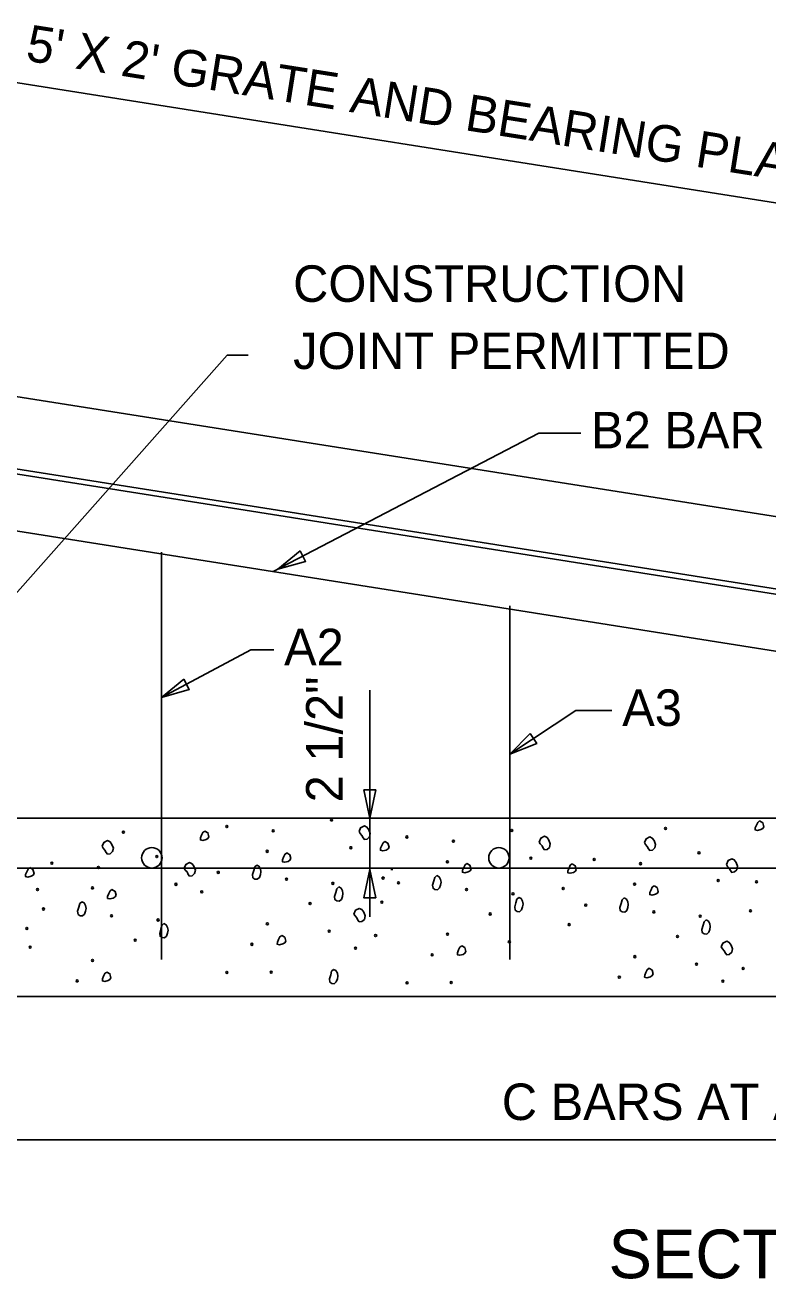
# Model space of a CAD drawing. Extents: x -439.1 to -407.9, y -458.1 to -436.2.
# Drawn here: x -435.33 to -432.28, y -450.33 to -445.18 of the extents above; entities that cross this region are included whole.
import ezdxf

# ---------------------------------------------------------------- set-up
doc = ezdxf.new("R2010")
doc.units = 0
doc.layers.add('Level 4', color=7, linetype='Continuous')
doc.layers.add('Level 45', color=7, linetype='Continuous')

msp = doc.modelspace()

# ---------------------------------------------------------------- linework, layer by layer
at = {"layer": 'Level 4'}
for p, q in [((-435.643, -445.37), (-430.4863, -446.1867)), ((-438.971, -446.1333), (-425.1939, -448.3149)), ((-436.1881, -448.4367), (-434.502, -446.5338)), ((-434.502, -446.5338), (-434.4147, -446.5338)), ((-434.3122, -447.4238), (-433.2211, -446.854)), ((-433.2211, -446.854), (-433.0485, -446.854)), ((-435.9228, -446.9132), (-430.76, -447.7311)), ((-435.9281, -446.9342), (-430.7645, -447.7516)), ((-436.074, -447.1452), (-430.0008, -448.107)), ((-434.771, -447.3437), (-434.771, -449.0184)), ((-433.3398, -447.5642), (-433.3398, -449.0184)), ((-434.771, -447.9417), (-434.4048, -447.7456)), ((-434.4048, -447.7456), (-434.3101, -447.7456)), ((-433.9151, -448.8431), (-433.9151, -447.9106)), ((-433.3398, -448.1734), (-433.0688, -447.995)), ((-433.0688, -447.995), (-432.9207, -447.995)), ((-435.9228, -448.4367), (-425.1939, -448.4367)), ((-436.4384, -448.6425), (-430.5353, -448.6425)), ((-433.8294, -448.6488), (-433.8206, -448.6488)), ((-436.7019, -449.1696), (-425.1939, -449.1696)), ((-425.1938, -449.759), (-436.7024, -449.759))]:
    msp.add_line(p, q, dxfattribs=at)
for points in [[(-434.2018, -447.3389), (-434.2936, -447.4141), (-434.1794, -447.3817)], [(-434.6799, -447.8656), (-434.771, -447.9417), (-434.6572, -447.9081)], [(-433.2561, -448.0893), (-433.3398, -448.1734), (-433.2295, -448.1296)], [(-433.9393, -448.3209), (-433.9151, -448.437), (-433.891, -448.3209)], [(-433.9596, -448.4922), (-433.953, -448.4764), (-433.9375, -448.4688), (-433.9272, -448.4737), (-433.9193, -448.4844), (-433.9136, -448.4996), (-433.9167, -448.5142), (-433.9268, -448.5231), (-433.9375, -448.5246), (-433.943, -448.5176), (-433.9479, -448.5078), (-433.9549, -448.5002), (-433.9596, -448.4922)], [(-432.3136, -448.4487), (-432.3214, -448.4546), (-432.3266, -448.4656), (-432.3314, -448.4768), (-432.3318, -448.4851), (-432.3223, -448.4874), (-432.3084, -448.4838), (-432.3007, -448.479), (-432.2967, -448.4721), (-432.301, -448.4561), (-432.3136, -448.4487)], [(-435.0152, -448.5528), (-435.0086, -448.537), (-434.9931, -448.5294), (-434.9828, -448.5343), (-434.9749, -448.545), (-434.9692, -448.5602), (-434.9723, -448.5748), (-434.9824, -448.5837), (-434.9931, -448.5852), (-434.9985, -448.5782), (-435.0035, -448.5683), (-435.0105, -448.5608), (-435.0152, -448.5528)], [(-434.5934, -448.4899), (-434.6012, -448.4958), (-434.6064, -448.5068), (-434.6112, -448.518), (-434.6116, -448.5263), (-434.6021, -448.5286), (-434.5882, -448.525), (-434.5805, -448.5202), (-434.5765, -448.5133), (-434.5808, -448.4973), (-434.5934, -448.4899)], [(-433.2195, -448.5352), (-433.2129, -448.5195), (-433.1974, -448.5118), (-433.1871, -448.5167), (-433.1793, -448.5274), (-433.1736, -448.5427), (-433.1767, -448.5573), (-433.1867, -448.5661), (-433.1974, -448.5677), (-433.2029, -448.5606), (-433.2078, -448.5508), (-433.2148, -448.5432), (-433.2195, -448.5352)], [(-432.787, -448.5374), (-432.7804, -448.5216), (-432.7649, -448.514), (-432.7546, -448.5189), (-432.7467, -448.5296), (-432.7411, -448.5449), (-432.7442, -448.5594), (-432.7542, -448.5683), (-432.7649, -448.5698), (-432.7704, -448.5628), (-432.7753, -448.553), (-432.7823, -448.5454), (-432.787, -448.5374)], [(-434.2564, -448.5799), (-434.2642, -448.5858), (-434.2694, -448.5968), (-434.2741, -448.608), (-434.2746, -448.6163), (-434.2651, -448.6186), (-434.2512, -448.615), (-434.2434, -448.6102), (-434.2395, -448.6033), (-434.2438, -448.5874), (-434.2564, -448.5799)], [(-433.8534, -448.533), (-433.8611, -448.5388), (-433.8663, -448.5498), (-433.8711, -448.5611), (-433.8715, -448.5693), (-433.8621, -448.5716), (-433.8482, -448.568), (-433.8404, -448.5632), (-433.8365, -448.5563), (-433.8407, -448.5404), (-433.8534, -448.533)], [(-434.6781, -448.6428), (-434.6715, -448.627), (-434.6561, -448.6194), (-434.6458, -448.6243), (-434.6379, -448.635), (-434.6322, -448.6502), (-434.6353, -448.6648), (-434.6453, -448.6737), (-434.6561, -448.6752), (-434.6615, -448.6682), (-434.6664, -448.6583), (-434.6734, -448.6508), (-434.6781, -448.6428)], [(-434.3802, -448.63), (-434.3881, -448.6375), (-434.3919, -448.6521), (-434.3972, -448.6689), (-434.3958, -448.682), (-434.3876, -448.6876), (-434.3776, -448.6884), (-434.3692, -448.6811), (-434.3646, -448.669), (-434.3628, -448.6572), (-434.3646, -448.6456), (-434.3707, -448.6348), (-434.3802, -448.63)], [(-433.5163, -448.623), (-433.5241, -448.6289), (-433.5293, -448.6398), (-433.534, -448.6511), (-433.5345, -448.6593), (-433.525, -448.6616), (-433.5111, -448.658), (-433.5033, -448.6532), (-433.4994, -448.6463), (-433.5037, -448.6304), (-433.5163, -448.623)], [(-433.0838, -448.6251), (-433.0916, -448.631), (-433.0968, -448.642), (-433.1015, -448.6532), (-433.102, -448.6615), (-433.0925, -448.6638), (-433.0786, -448.6602), (-433.0708, -448.6554), (-433.0669, -448.6485), (-433.0712, -448.6326), (-433.0838, -448.6251)], [(-432.4499, -448.6274), (-432.4434, -448.6116), (-432.4279, -448.604), (-432.4176, -448.6089), (-432.4097, -448.6196), (-432.404, -448.6349), (-432.4071, -448.6494), (-432.4172, -448.6583), (-432.4279, -448.6598), (-432.4333, -448.6528), (-432.4383, -448.643), (-432.4453, -448.6354), (-432.4499, -448.6274)], [(-435.312, -448.6405), (-435.3198, -448.6464), (-435.325, -448.6574), (-435.3297, -448.6686), (-435.3302, -448.6769), (-435.3207, -448.6792), (-435.3068, -448.6756), (-435.299, -448.6708), (-435.2951, -448.6639), (-435.2994, -448.6479), (-435.312, -448.6405)], [(-433.891, -448.7649), (-433.9151, -448.6488), (-433.9393, -448.7649)], [(-433.6401, -448.6731), (-433.6481, -448.6805), (-433.6518, -448.6951), (-433.6571, -448.7119), (-433.6557, -448.725), (-433.6475, -448.7306), (-433.6375, -448.7315), (-433.6291, -448.7241), (-433.6246, -448.712), (-433.6227, -448.7003), (-433.6246, -448.6886), (-433.6306, -448.6778), (-433.6401, -448.6731)], [(-434.9749, -448.7305), (-434.9827, -448.7364), (-434.9879, -448.7474), (-434.9927, -448.7586), (-434.9931, -448.7669), (-434.9836, -448.7692), (-434.9697, -448.7656), (-434.962, -448.7608), (-434.9581, -448.7539), (-434.9623, -448.7379), (-434.9749, -448.7305)], [(-434.0432, -448.72), (-434.0511, -448.7275), (-434.0548, -448.7421), (-434.0602, -448.7589), (-434.0587, -448.772), (-434.0506, -448.7776), (-434.0406, -448.7785), (-434.0321, -448.7711), (-434.0276, -448.759), (-434.0258, -448.7472), (-434.0276, -448.7356), (-434.0336, -448.7248), (-434.0432, -448.72)], [(-432.7468, -448.7151), (-432.7546, -448.721), (-432.7598, -448.732), (-432.7645, -448.7432), (-432.7649, -448.7515), (-432.7555, -448.7538), (-432.7416, -448.7502), (-432.7338, -448.7454), (-432.7299, -448.7385), (-432.7341, -448.7226), (-432.7468, -448.7151)], [(-435.0988, -448.7806), (-435.1067, -448.7881), (-435.1104, -448.8027), (-435.1158, -448.8195), (-435.1143, -448.8326), (-435.1061, -448.8382), (-435.0962, -448.839), (-435.0877, -448.8317), (-435.0832, -448.8196), (-435.0814, -448.8078), (-435.0832, -448.7962), (-435.0892, -448.7854), (-435.0988, -448.7806)], [(-433.3031, -448.7631), (-433.311, -448.7705), (-433.3148, -448.7851), (-433.3201, -448.8019), (-433.3187, -448.815), (-433.3105, -448.8206), (-433.3005, -448.8215), (-433.2921, -448.8141), (-433.2875, -448.802), (-433.2857, -448.7903), (-433.2875, -448.7786), (-433.2935, -448.7678), (-433.3031, -448.7631)], [(-432.8706, -448.7652), (-432.8785, -448.7727), (-432.8823, -448.7873), (-432.8876, -448.8041), (-432.8862, -448.8172), (-432.878, -448.8228), (-432.868, -448.8237), (-432.8596, -448.8163), (-432.855, -448.8042), (-432.8532, -448.7924), (-432.855, -448.7808), (-432.861, -448.77), (-432.8706, -448.7652)], [(-433.9806, -448.8311), (-433.9741, -448.8154), (-433.9586, -448.8078), (-433.9483, -448.8126), (-433.9404, -448.8233), (-433.9347, -448.8386), (-433.9378, -448.8532), (-433.9478, -448.862), (-433.9586, -448.8636), (-433.964, -448.8565), (-433.9689, -448.8467), (-433.9759, -448.8391), (-433.9806, -448.8311)], [(-434.7617, -448.8706), (-434.7697, -448.8781), (-434.7734, -448.8927), (-434.7787, -448.9095), (-434.7773, -448.9226), (-434.7691, -448.9282), (-434.7591, -448.929), (-434.7507, -448.9217), (-434.7461, -448.9096), (-434.7443, -448.8978), (-434.7461, -448.8862), (-434.7522, -448.8754), (-434.7617, -448.8706)], [(-432.5336, -448.8552), (-432.5415, -448.8627), (-432.5452, -448.8773), (-432.5505, -448.8941), (-432.5491, -448.9072), (-432.5409, -448.9128), (-432.531, -448.9137), (-432.5225, -448.9063), (-432.518, -448.8942), (-432.5162, -448.8825), (-432.518, -448.8708), (-432.524, -448.86), (-432.5336, -448.8552)], [(-434.2774, -448.9189), (-434.2852, -448.9248), (-434.2904, -448.9358), (-434.2952, -448.947), (-434.2956, -448.9552), (-434.2861, -448.9576), (-434.2723, -448.9539), (-434.2645, -448.9492), (-434.2606, -448.9422), (-434.2648, -448.9263), (-434.2774, -448.9189)], [(-432.471, -448.9663), (-432.4644, -448.9506), (-432.449, -448.943), (-432.4387, -448.9478), (-432.4308, -448.9586), (-432.4251, -448.9738), (-432.4282, -448.9884), (-432.4382, -448.9972), (-432.449, -448.9988), (-432.4544, -448.9917), (-432.4593, -448.9819), (-432.4663, -448.9743), (-432.471, -448.9663)], [(-433.5374, -448.9619), (-433.5452, -448.9678), (-433.5504, -448.9788), (-433.5551, -448.99), (-433.5555, -448.9983), (-433.5461, -449.0006), (-433.5322, -448.997), (-433.5244, -448.9922), (-433.5205, -448.9853), (-433.5247, -448.9693), (-433.5374, -448.9619)], [(-434.996, -449.0695), (-435.0038, -449.0754), (-435.009, -449.0864), (-435.0137, -449.0976), (-435.0142, -449.1058), (-435.0047, -449.1082), (-434.9908, -449.1045), (-434.983, -449.0998), (-434.9791, -449.0928), (-434.9834, -449.0769), (-434.996, -449.0695)], [(-434.0642, -449.059), (-434.0722, -449.0664), (-434.0759, -449.0811), (-434.0812, -449.0978), (-434.0798, -449.1109), (-434.0716, -449.1165), (-434.0616, -449.1174), (-434.0532, -449.11), (-434.0487, -449.0979), (-434.0468, -449.0862), (-434.0487, -449.0746), (-434.0547, -449.0638), (-434.0642, -449.059)], [(-432.7678, -449.0541), (-432.7756, -449.06), (-432.7808, -449.071), (-432.7856, -449.0822), (-432.786, -449.0904), (-432.7765, -449.0928), (-432.7626, -449.0891), (-432.7549, -449.0844), (-432.751, -449.0775), (-432.7552, -449.0615), (-432.7678, -449.0541)]]:
    msp.add_lwpolyline(points, close=True, dxfattribs=at)
for centre in [(-434.811, -448.6), (-433.3849, -448.6)]:
    msp.add_circle(centre, 0.042, dxfattribs=at)
for centre, start, end in [((-434.503, -448.4714), 0, 180), ((-434.503, -448.4714), 180, 0), ((-434.0723, -448.4445), 0, 180), ((-434.0723, -448.4445), 180, 0), ((-432.6999, -448.4793), 0, 180), ((-432.6999, -448.4793), 180, 0), ((-434.928, -448.4946), 0, 180), ((-434.928, -448.4946), 180, 0), ((-434.3122, -448.489), 0, 180), ((-434.3122, -448.489), 180, 0), ((-433.7629, -448.5145), 0, 180), ((-433.7629, -448.5145), 180, 0), ((-433.5721, -448.532), 0, 180), ((-433.3323, -448.4875), 0, 180), ((-433.3323, -448.4875), 180, 0), ((-434.3368, -448.5735), 0, 180), ((-434.3368, -448.5735), 180, 0), ((-433.9934, -448.5585), 0, 180), ((-433.9934, -448.5585), 180, 0), ((-433.5721, -448.532), 180, 0), ((-432.5627, -448.5797), 0, 180), ((-432.5627, -448.5797), 180, 0), ((-435.2215, -448.622), 0, 180), ((-435.2215, -448.622), 180, 0), ((-434.7909, -448.5951), 0, 180), ((-434.7909, -448.5951), 180, 0), ((-433.5967, -448.6165), 0, 180), ((-433.5967, -448.6165), 180, 0), ((-433.2533, -448.6016), 0, 180), ((-433.2533, -448.6016), 180, 0), ((-432.9933, -448.6067), 0, 180), ((-432.9933, -448.6067), 180, 0), ((-432.8026, -448.6242), 0, 180), ((-432.8026, -448.6242), 180, 0), ((-435.0307, -448.6396), 0, 180), ((-435.0307, -448.6396), 180, 0), ((-434.5379, -448.6599), 0, 180), ((-434.5379, -448.6599), 180, 0), ((-434.2578, -448.6875), 0, 180), ((-433.8611, -448.6832), 0, 180), ((-433.8611, -448.6832), 180, 0), ((-435.281, -448.7305), 0, 180), ((-435.281, -448.7305), 180, 0), ((-435.0553, -448.7241), 0, 180), ((-435.0553, -448.7241), 180, 0), ((-434.7119, -448.7091), 0, 180), ((-434.7119, -448.7091), 180, 0), ((-434.6061, -448.7396), 0, 180), ((-434.2578, -448.6875), 180, 0), ((-434.0671, -448.7051), 0, 180), ((-434.0671, -448.7051), 180, 0), ((-433.7979, -448.703), 0, 180), ((-433.7979, -448.703), 180, 0), ((-433.5178, -448.7306), 0, 180), ((-433.5178, -448.7306), 180, 0), ((-433.121, -448.7262), 0, 180), ((-433.121, -448.7262), 180, 0), ((-432.8272, -448.7087), 0, 180), ((-432.8272, -448.7087), 180, 0), ((-432.4838, -448.6937), 0, 180), ((-432.4838, -448.6937), 180, 0), ((-432.3263, -448.6984), 0, 180), ((-432.3263, -448.6984), 180, 0), ((-434.6061, -448.7396), 180, 0), ((-434.161, -448.788), 0, 180), ((-434.161, -448.788), 180, 0), ((-433.866, -448.7826), 0, 180), ((-433.866, -448.7826), 180, 0), ((-433.327, -448.7481), 0, 180), ((-433.327, -448.7481), 180, 0), ((-435.2565, -448.8105), 0, 180), ((-435.2565, -448.8105), 180, 0), ((-434.9764, -448.8381), 0, 180), ((-434.9764, -448.8381), 180, 0), ((-433.4209, -448.831), 0, 180), ((-433.4209, -448.831), 180, 0), ((-433.0283, -448.7951), 0, 180), ((-433.0283, -448.7951), 180, 0), ((-432.7482, -448.8227), 0, 180), ((-432.7482, -448.8227), 180, 0), ((-432.5575, -448.8403), 0, 180), ((-432.5575, -448.8403), 180, 0), ((-432.3515, -448.8184), 0, 180), ((-432.3515, -448.8184), 180, 0), ((-435.3246, -448.8902), 0, 180), ((-435.3246, -448.8902), 180, 0), ((-434.7856, -448.8557), 0, 180), ((-434.7856, -448.8557), 180, 0), ((-434.3364, -448.8712), 0, 180), ((-434.3364, -448.8712), 180, 0), ((-433.0965, -448.8748), 0, 180), ((-433.0965, -448.8748), 180, 0), ((-434.8796, -448.9386), 0, 180), ((-434.8796, -448.9386), 180, 0), ((-434.0821, -448.902), 0, 180), ((-434.0821, -448.902), 180, 0), ((-433.8913, -448.9196), 0, 180), ((-433.8913, -448.9196), 180, 0), ((-433.5963, -448.9142), 0, 180), ((-433.5963, -448.9142), 180, 0), ((-433.342, -448.945), 0, 180), ((-432.6514, -448.9232), 0, 180), ((-432.6514, -448.9232), 180, 0), ((-435.3112, -448.9669), 0, 180), ((-435.3112, -448.9669), 180, 0), ((-434.3997, -448.9557), 0, 180), ((-434.3997, -448.9557), 180, 0), ((-433.974, -448.9718), 0, 180), ((-433.974, -448.9718), 180, 0), ((-433.6596, -448.9987), 0, 180), ((-433.342, -448.945), 180, 0), ((-435.0549, -449.0218), 0, 180), ((-435.0549, -449.0218), 180, 0), ((-433.6596, -448.9987), 180, 0), ((-432.8268, -449.0064), 0, 180), ((-432.8268, -449.0064), 180, 0), ((-432.5725, -449.0372), 0, 180), ((-432.5725, -449.0372), 180, 0), ((-434.5025, -449.0711), 0, 180), ((-434.5025, -449.0711), 180, 0), ((-434.3207, -449.0697), 0, 180), ((-434.3207, -449.0697), 180, 0), ((-432.8901, -449.0909), 0, 180), ((-432.8901, -449.0909), 180, 0), ((-432.3817, -449.0548), 0, 180), ((-432.3817, -449.0548), 180, 0), ((-435.1182, -449.1063), 0, 180), ((-435.1182, -449.1063), 180, 0), ((-433.7624, -449.1142), 0, 180), ((-433.7624, -449.1142), 180, 0), ((-433.5807, -449.1127), 0, 180), ((-433.5807, -449.1127), 180, 0), ((-432.4643, -449.107), 0, 180), ((-432.4643, -449.107), 180, 0)]:
    msp.add_arc(centre, 0.00416, start, end, dxfattribs=at)

# ---------------------------------------------------------------- texts
for s, height, p in [('CONSTRUCTION ', 0.15, (-434.2304, -446.3149)), ('JOINT PERMITTED', 0.15, (-434.2304, -446.5909)), ('B2 BAR', 0.15, (-433.0059, -446.917)), ('A2', 0.15, (-434.2676, -447.8086)), ('A3', 0.15, (-432.8782, -448.058)), ('SECTION B-B', 0.2, (-432.9346, -450.3282))]:
    msp.add_text(s, height=height, dxfattribs=at).set_placement(p)
at = {"layer": 'Level 45'}
for s, rotation, p in [("5' X 2' GRATE AND BEARING PLATE", 351, (-435.3332, -445.3228)), ('2 1/2"', 90, (-434.0272, -448.3723))]:
    msp.add_text(s, height=0.15, rotation=rotation, dxfattribs=at).set_placement(p)
msp.add_text('C BARS AT APPROXIMATELY 16" CTRS.', height=0.15, dxfattribs=at).set_placement((-433.3729, -449.6779))

doc.saveas('drawing.dxf')
